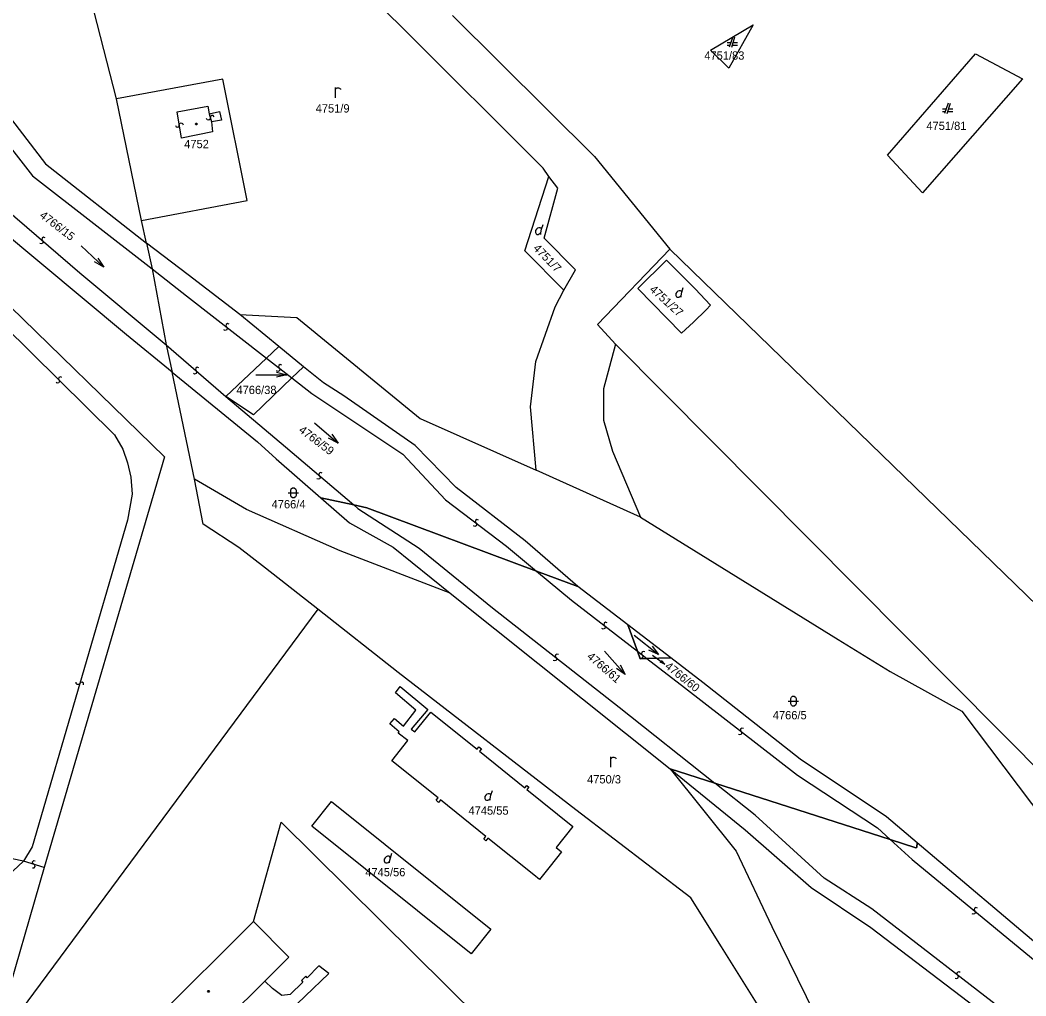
# Model space of a CAD drawing. Extents: x -266179 to -264727, y -1243225 to -1241702.
# Drawn here: x -265424.6 to -265230.4, y -1242086.5 to -1241898.2 of the extents above; entities that cross this region are included whole.
import ezdxf

# ---------------------------------------------------------------- set-up
doc = ezdxf.new("R2010")
doc.units = 0
doc.layers.add('Vrstva 1', color=7, linetype='Continuous')
doc.layers.add('Vrstva 2', color=7, linetype='Continuous')

msp = doc.modelspace()

# ---------------------------------------------------------------- linework, layer by layer
at = {"layer": 'Vrstva 1'}
for p, q in [((-265409.1, -1241901.41), (-265419.8, -1241859.01)), ((-265350.81, -1241899.67), (-265380.43, -1241870.51)), ((-265341.11, -1241897.34), (-265313.71, -1241924.53)), ((-265323.64, -1241926.77), (-265350.81, -1241899.67)), ((-265291.31, -1241904.02), (-265283.1, -1241899.12)), ((-265283.1, -1241899.12), (-265287.8, -1241907.53)), ((-265405.98, -1241913.4), (-265409.1, -1241901.41)), ((-265287.02, -1241901.44), (-265287.72, -1241903.44)), ((-265287.22, -1241903.44), (-265286.62, -1241901.44)), ((-265287.44, -1241902.64), (-265288.12, -1241902.64)), ((-265288.12, -1241903.04), (-265287.58, -1241903.04)), ((-265287.1, -1241903.04), (-265286.12, -1241903.04)), ((-265286.12, -1241902.64), (-265286.98, -1241902.64)), ((-265287.8, -1241907.53), (-265291.31, -1241904.02)), ((-265257.12, -1241924.32), (-265240.18, -1241904.71)), ((-265240.18, -1241904.71), (-265231.07, -1241909.59)), ((-265385.49, -1241909.62), (-265405.98, -1241913.4)), ((-265380.74, -1241933.05), (-265385.49, -1241909.62)), ((-265231.07, -1241909.59), (-265250.38, -1241931.54)), ((-265401.15, -1241936.9), (-265405.98, -1241913.4)), ((-265427.71, -1241915.45), (-265419.67, -1241925.96)), ((-265245.83, -1241915.44), (-265246.51, -1241915.44)), ((-265245.41, -1241914.24), (-265246.11, -1241916.24)), ((-265245.61, -1241916.24), (-265245.01, -1241914.24)), ((-265244.51, -1241915.44), (-265245.37, -1241915.44)), ((-265246.51, -1241915.84), (-265245.97, -1241915.84)), ((-265245.49, -1241915.84), (-265244.51, -1241915.84)), ((-265313.71, -1241924.53), (-265299.18, -1241942.46)), ((-265250.38, -1241931.54), (-265257.12, -1241924.32)), ((-265453.67, -1241927.03), (-265396.73, -1241982.53)), ((-265419.67, -1241925.96), (-265400.17, -1241941.28)), ((-265322.52, -1241928.38), (-265323.64, -1241926.77)), ((-265327.13, -1241942.78), (-265322.52, -1241928.38)), ((-265320.78, -1241930.65), (-265322.52, -1241928.38)), ((-265323.44, -1241940.32), (-265320.78, -1241930.65)), ((-265401.15, -1241936.9), (-265380.74, -1241933.05)), ((-265400.17, -1241941.28), (-265401.15, -1241936.9)), ((-265404.08, -1241958.98), (-265429.11, -1241938.09)), ((-265323.92, -1241938.58), (-265323.65, -1241937.68)), ((-265317.35, -1241946.43), (-265323.44, -1241940.32)), ((-265412.796, -1241941.764), (-265408.464, -1241945.916)), ((-265392.18, -1241947.36), (-265400.17, -1241941.28)), ((-265400.17, -1241941.28), (-265399.12, -1241946.23)), ((-265299.18, -1241942.46), (-265313.16, -1241956.94)), ((-265299.18, -1241942.46), (-265107.1, -1242128.74)), ((-265319.6, -1241950.32), (-265327.13, -1241942.78)), ((-265305.36, -1241950.05), (-265299.79, -1241944.58)), ((-265299.79, -1241944.58), (-265294.28, -1241950.11)), ((-265399.12, -1241946.23), (-265396.38, -1241960.9)), ((-265319.6, -1241950.32), (-265317.35, -1241946.43)), ((-265382.2, -1241955.06), (-265392.18, -1241947.36)), ((-265321.32, -1241953.55), (-265319.6, -1241950.32)), ((-265296.91, -1241958.67), (-265305.36, -1241950.05)), ((-265296.83, -1241950.72), (-265296.56, -1241949.82)), ((-265294.28, -1241950.11), (-265291.3, -1241953.23)), ((-265325.01, -1241964.12), (-265321.32, -1241953.55)), ((-265292.17, -1241954.15), (-265294.61, -1241956.49)), ((-265291.3, -1241953.23), (-265292.17, -1241954.15)), ((-265374.65, -1241961.21), (-265382.2, -1241955.06)), ((-265382.2, -1241955.06), (-265371.17, -1241955.6)), ((-265371.17, -1241955.6), (-265347.38, -1241975.13)), ((-265313.16, -1241956.94), (-265309.66, -1241960.74)), ((-265294.61, -1241956.49), (-265296.91, -1241958.67)), ((-265395.25, -1241966.18), (-265404.08, -1241958.98)), ((-265396.38, -1241960.9), (-265395.25, -1241966.18)), ((-265377.03, -1241963.45), (-265374.65, -1241961.21)), ((-265369.87, -1241965.11), (-265374.65, -1241961.21)), ((-265309.66, -1241960.74), (-265311.94, -1241969.4)), ((-265125.85, -1242145.82), (-265309.66, -1241960.74)), ((-265384.86, -1241970.84), (-265377.03, -1241963.45)), ((-265369.87, -1241965.11), (-265372.12, -1241967.27)), ((-265366.05, -1241968.22), (-265369.87, -1241965.11)), ((-265326.07, -1241972.85), (-265325.01, -1241964.12)), ((-265390.93, -1241986.84), (-265395.25, -1241966.18)), ((-265395.25, -1241966.18), (-265378.76, -1241979.64)), ((-265372.12, -1241967.27), (-265379.57, -1241974.41)), ((-265379.11, -1241966.65), (-265373.11, -1241966.65)), ((-265362.08, -1241970.73), (-265366.05, -1241968.22)), ((-265311.94, -1241969.4), (-265311.94, -1241975.4)), ((-265379.57, -1241974.41), (-265384.86, -1241970.84)), ((-265348.33, -1241980.33), (-265362.08, -1241970.73)), ((-265324.99, -1241985.06), (-265326.07, -1241972.85)), ((-265347.38, -1241975.13), (-265324.99, -1241985.06)), ((-265311.94, -1241975.4), (-265310.26, -1241981.4)), ((-265367.743, -1241975.922), (-265363.197, -1241979.838)), ((-265378.76, -1241979.64), (-265375.17, -1241982.89)), ((-265340.42, -1241988.44), (-265348.33, -1241980.33)), ((-265310.26, -1241981.4), (-265304.8, -1241994.15)), ((-265396.73, -1241982.53), (-265419.94, -1242061.77)), ((-265375.17, -1241982.89), (-265366.55, -1241990.42)), ((-265304.8, -1241994.15), (-265324.99, -1241985.06)), ((-265380.87, -1241992.68), (-265390.93, -1241986.84)), ((-265389.24, -1241995.49), (-265390.93, -1241986.84)), ((-265327.09, -1241998.73), (-265340.42, -1241988.44)), ((-265366.55, -1241990.42), (-265361.03, -1241995.25)), ((-265360.2, -1241991.78), (-265366.55, -1241990.42)), ((-265366.55, -1241990.42), (-265360.2, -1241991.78)), ((-265362.83, -1242000.62), (-265380.87, -1241992.68)), ((-265357.68, -1241992.32), (-265360.2, -1241991.78)), ((-265360.2, -1241991.78), (-265357.68, -1241992.32)), ((-265324.9, -1242004.54), (-265357.68, -1241992.32)), ((-265357.68, -1241992.32), (-265324.9, -1242004.54)), ((-265304.8, -1241994.15), (-265266.64, -1242017.73)), ((-265382.38, -1241999.97), (-265389.24, -1241995.49)), ((-265361.03, -1241995.25), (-265352.57, -1241999.96)), ((-265316.9, -1242007.52), (-265327.09, -1241998.73)), ((-265377.22, -1242004), (-265382.38, -1241999.97)), ((-265341.55, -1242008.84), (-265362.83, -1242000.62)), ((-265352.57, -1241999.96), (-265341.55, -1242008.84)), ((-265367.1, -1242011.91), (-265377.22, -1242004)), ((-265316.9, -1242007.52), (-265324.9, -1242004.54)), ((-265324.9, -1242004.54), (-265316.9, -1242007.52)), ((-265307.27, -1242014.93), (-265316.9, -1242007.52)), ((-265341.55, -1242008.84), (-265299.12, -1242042.71)), ((-265367.1, -1242011.91), (-265434.24, -1242102.45)), ((-265351.59, -1242024.1), (-265367.1, -1242011.91)), ((-265298.99, -1242021.3), (-265307.27, -1242014.93)), ((-265305.4, -1242020.02), (-265307.27, -1242014.93)), ((-265307.27, -1242014.93), (-265305.4, -1242020.02)), ((-265306.049, -1242016.946), (-265301.331, -1242020.654)), ((-265266.64, -1242017.73), (-265256.62, -1242023.96)), ((-265311.78, -1242020.024), (-265307.78, -1242024.496)), ((-265304.87, -1242021.46), (-265305.4, -1242020.02)), ((-265305.4, -1242020.02), (-265304.87, -1242021.46)), ((-265303.59, -1242021.43), (-265304.87, -1242021.46)), ((-265304.87, -1242021.46), (-265303.59, -1242021.43)), ((-265298.99, -1242021.3), (-265303.59, -1242021.43)), ((-265303.59, -1242021.43), (-265298.99, -1242021.3)), ((-265300.805, -1242021.781), (-265300.121, -1242022.538)), ((-265292.79, -1242026.07), (-265298.99, -1242021.3)), ((-265317.31, -1242050.61), (-265351.59, -1242024.1)), ((-265256.62, -1242023.96), (-265242.79, -1242031.59)), ((-265273.99, -1242040.84), (-265292.79, -1242026.07)), ((-265352.15, -1242028.05), (-265351.23, -1242026.82)), ((-265348.17, -1242031.4), (-265352.15, -1242028.05)), ((-265351.23, -1242026.82), (-265345.89, -1242031.24)), ((-265350.61, -1242034.5), (-265348.17, -1242031.4)), ((-265345.89, -1242031.24), (-265349.11, -1242035.03)), ((-265348.39, -1242035.56), (-265345.32, -1242031.75)), ((-265345.32, -1242031.75), (-265336.39, -1242038.94)), ((-265242.79, -1242031.59), (-265226.55, -1242053.07)), ((-265353.19, -1242034), (-265352.32, -1242032.98)), ((-265352.32, -1242032.98), (-265350.61, -1242034.5)), ((-265351.45, -1242035.57), (-265353.19, -1242034)), ((-265351.63, -1242035.85), (-265351.45, -1242035.57)), ((-265349.75, -1242037.24), (-265351.63, -1242035.85)), ((-265349.11, -1242035.03), (-265348.39, -1242035.56)), ((-265352.85, -1242041.14), (-265349.75, -1242037.24)), ((-265336.39, -1242038.94), (-265336.01, -1242038.47)), ((-265336.01, -1242038.47), (-265335.53, -1242038.86)), ((-265335.53, -1242038.86), (-265335.91, -1242039.33)), ((-265335.91, -1242039.33), (-265327.17, -1242046.37)), ((-265343.91, -1242048.32), (-265352.85, -1242041.14)), ((-265257.33, -1242052), (-265273.99, -1242040.84)), ((-265299.12, -1242042.71), (-265286.37, -1242058.58)), ((-265299.12, -1242042.71), (-265284.63, -1242054.46)), ((-265290.46, -1242045.49), (-265299.12, -1242042.71)), ((-265299.12, -1242042.71), (-265290.46, -1242045.49)), ((-265256.63, -1242056.36), (-265290.46, -1242045.49)), ((-265290.46, -1242045.49), (-265256.63, -1242056.36)), ((-265333.69, -1242047.79), (-265333.42, -1242046.89)), ((-265327.17, -1242046.37), (-265326.79, -1242045.9)), ((-265326.79, -1242045.9), (-265326.37, -1242046.24)), ((-265326.37, -1242046.24), (-265326.75, -1242046.7)), ((-265326.75, -1242046.7), (-265317.88, -1242053.85)), ((-265368.29, -1242053.78), (-265364.47, -1242049.02)), ((-265364.47, -1242049.02), (-265333.7, -1242073.65)), ((-265344.28, -1242048.79), (-265343.91, -1242048.32)), ((-265343.81, -1242049.19), (-265344.28, -1242048.79)), ((-265343.43, -1242048.71), (-265343.81, -1242049.19)), ((-265334.69, -1242055.74), (-265343.43, -1242048.71)), ((-265295.11, -1242067.63), (-265317.31, -1242050.61)), ((-265379.52, -1242072.17), (-265374.2, -1242053.02)), ((-265374.2, -1242053.02), (-265286.2, -1242140.05)), ((-265251.43, -1242056.99), (-265257.33, -1242052)), ((-265337.49, -1242078.4), (-265368.29, -1242053.78)), ((-265317.88, -1242053.85), (-265321.14, -1242057.9)), ((-265284.63, -1242054.46), (-265271.86, -1242065.62)), ((-265335.09, -1242056.22), (-265334.69, -1242055.74)), ((-265334.68, -1242056.58), (-265335.09, -1242056.22)), ((-265334.27, -1242056.08), (-265334.68, -1242056.58)), ((-265325.41, -1242063.2), (-265334.27, -1242056.08)), ((-265251.67, -1242057.95), (-265256.63, -1242056.36)), ((-265256.63, -1242056.36), (-265251.67, -1242057.95)), ((-265251.43, -1242056.99), (-265251.46, -1242057.82)), ((-265251.46, -1242057.82), (-265251.43, -1242056.99)), ((-265224.35, -1242079.9), (-265251.43, -1242056.99)), ((-265353.12, -1242059.86), (-265352.85, -1242058.96)), ((-265320.09, -1242058.75), (-265322.28, -1242061.48)), ((-265321.14, -1242057.9), (-265320.09, -1242058.75)), ((-265286.37, -1242058.58), (-265279.5, -1242073.11)), ((-265251.46, -1242057.82), (-265251.67, -1242057.95)), ((-265251.67, -1242057.95), (-265251.46, -1242057.82)), ((-265419.94, -1242061.77), (-265429.51, -1242094.71)), ((-265322.28, -1242061.48), (-265324.32, -1242064.08)), ((-265324.32, -1242064.08), (-265325.41, -1242063.2)), ((-265271.86, -1242065.62), (-265260.34, -1242073.33)), ((-265289.22, -1242077.06), (-265295.11, -1242067.63)), ((-265403.16, -1242095.63), (-265379.52, -1242072.17)), ((-265372.75, -1242079.05), (-265379.52, -1242072.17)), ((-265333.7, -1242073.65), (-265337.49, -1242078.4)), ((-265279.5, -1242073.11), (-265271.16, -1242090.08)), ((-265260.34, -1242073.33), (-265228.42, -1242097.62)), ((-265272.23, -1242104.07), (-265289.22, -1242077.06)), ((-265377.37, -1242083.7), (-265372.75, -1242079.05)), ((-265384.47, -1242100.74), (-265365.02, -1242082.22)), ((-265366.95, -1242080.73), (-265369.15, -1242083.05)), ((-265365.02, -1242082.22), (-265366.95, -1242080.73)), ((-265377.37, -1242083.7), (-265396.35, -1242102.47)), ((-265375.86, -1242085.08), (-265377.37, -1242083.7)), ((-265370.01, -1242083.9), (-265372.43, -1242086.29)), ((-265369.46, -1242082.73), (-265370.3, -1242083.57)), ((-265370.3, -1242083.57), (-265370.01, -1242083.9)), ((-265369.15, -1242083.05), (-265369.46, -1242082.73)), ((-265374.06, -1242086.44), (-265375.86, -1242085.08)), ((-265372.43, -1242086.29), (-265374.06, -1242086.44))]:
    msp.add_line(p, q, dxfattribs=at)
for points in [[(-265363.73, -1241913.2), (-265363.73, -1241911.93), (-265363.73, -1241911.2)], [(-265363.73, -1241911.6), (-265363.63, -1241911.47), (-265363.5, -1241911.36), (-265363.36, -1241911.31), (-265363.13, -1241911.3), (-265362.96, -1241911.33), (-265362.86, -1241911.4), (-265362.77, -1241911.5), (-265362.73, -1241911.6)], [(-265324.1, -1241939.57), (-265324.1, -1241939.3), (-265323.92, -1241938.58), (-265324.01, -1241938.4), (-265324.19, -1241938.31), (-265324.46, -1241938.31), (-265324.73, -1241938.4), (-265324.91, -1241938.58), (-265325.09, -1241938.85), (-265325.09, -1241939.21), (-265325, -1241939.48), (-265324.82, -1241939.57), (-265324.55, -1241939.57), (-265324.37, -1241939.48), (-265324.1, -1241939.3)], [(-265409.562, -1241944.171), (-265408.464, -1241945.916), (-265410.254, -1241944.893)], [(-265297.01, -1241951.71), (-265297.01, -1241951.44), (-265296.83, -1241950.72), (-265296.92, -1241950.54), (-265297.1, -1241950.45), (-265297.37, -1241950.45), (-265297.64, -1241950.54), (-265297.82, -1241950.72), (-265298, -1241950.99), (-265298, -1241951.35), (-265297.91, -1241951.62), (-265297.73, -1241951.71), (-265297.46, -1241951.71), (-265297.28, -1241951.62), (-265297.01, -1241951.44)], [(-265375.11, -1241966.15), (-265373.11, -1241966.65), (-265375.11, -1241967.15)], [(-265364.386, -1241978.154), (-265363.197, -1241979.838), (-265365.039, -1241978.912)], [(-265372.84, -1241989.45), (-265371.57, -1241989.45), (-265370.84, -1241989.45)], [(-265302.595, -1242019.025), (-265301.331, -1242020.654), (-265303.213, -1242019.811)], [(-265302.53, -1242020.75), (-265300.121, -1242022.538), (-265301.043, -1242022.102)], [(-265308.741, -1242022.672), (-265307.78, -1242024.496), (-265309.486, -1242023.339)], [(-265276.31, -1242029.66), (-265275.04, -1242029.66), (-265274.31, -1242029.66)], [(-265310.55, -1242042.38), (-265310.55, -1242041.11), (-265310.55, -1242040.38)], [(-265310.55, -1242040.78), (-265310.45, -1242040.65), (-265310.32, -1242040.54), (-265310.18, -1242040.49), (-265309.95, -1242040.48), (-265309.78, -1242040.51), (-265309.68, -1242040.58), (-265309.59, -1242040.68), (-265309.55, -1242040.78)], [(-265333.87, -1242048.78), (-265333.87, -1242048.51), (-265333.69, -1242047.79), (-265333.78, -1242047.61), (-265333.96, -1242047.52), (-265334.23, -1242047.52), (-265334.5, -1242047.61), (-265334.68, -1242047.79), (-265334.86, -1242048.06), (-265334.86, -1242048.42), (-265334.77, -1242048.69), (-265334.59, -1242048.78), (-265334.32, -1242048.78), (-265334.14, -1242048.69), (-265333.87, -1242048.51)], [(-265353.3, -1242060.85), (-265353.3, -1242060.58), (-265353.12, -1242059.86), (-265353.21, -1242059.68), (-265353.39, -1242059.59), (-265353.66, -1242059.59), (-265353.93, -1242059.68), (-265354.11, -1242059.86), (-265354.29, -1242060.13), (-265354.29, -1242060.49), (-265354.2, -1242060.76), (-265354.02, -1242060.85), (-265353.75, -1242060.85), (-265353.57, -1242060.76), (-265353.3, -1242060.58)]]:
    msp.add_lwpolyline(points, dxfattribs=at)
for points in [[(-265390.48, -1241918.14), (-265390.39, -1241918.29), (-265390.48, -1241918.44), (-265390.66, -1241918.44), (-265390.75, -1241918.29), (-265390.66, -1241918.14)], [(-265372.34, -1241988.95), (-265372.24, -1241988.66), (-265371.99, -1241988.48), (-265371.68, -1241988.48), (-265371.43, -1241988.66), (-265371.33, -1241988.95), (-265371.33, -1241989.95), (-265371.43, -1241990.24), (-265371.68, -1241990.42), (-265371.99, -1241990.42), (-265372.24, -1241990.24), (-265372.34, -1241989.95)], [(-265275.81, -1242029.16), (-265275.71, -1242028.87), (-265275.46, -1242028.69), (-265275.15, -1242028.69), (-265274.9, -1242028.87), (-265274.8, -1242029.16), (-265274.8, -1242030.16), (-265274.9, -1242030.45), (-265275.15, -1242030.63), (-265275.46, -1242030.63), (-265275.71, -1242030.45), (-265275.81, -1242030.16)], [(-265388.14, -1242085.5), (-265388.05, -1242085.65), (-265388.14, -1242085.8), (-265388.32, -1242085.8), (-265388.41, -1242085.65), (-265388.32, -1242085.5)]]:
    msp.add_lwpolyline(points, close=True, dxfattribs=at)
at = {"layer": 'Vrstva 2'}
for p, q in [((-265432.81, -1241914.75), (-265422.2, -1241928.26)), ((-265394.28, -1241915.94), (-265388.34, -1241914.84)), ((-265388.34, -1241914.84), (-265388.12, -1241916.29)), ((-265393.46, -1241921.03), (-265394.28, -1241915.94)), ((-265388.12, -1241916.29), (-265386.11, -1241915.87)), ((-265388.12, -1241916.29), (-265387.67, -1241917.87)), ((-265386.11, -1241915.87), (-265385.74, -1241917.52)), ((-265385.74, -1241917.52), (-265387.67, -1241917.87)), ((-265387.67, -1241917.87), (-265387.45, -1241919.79)), ((-265387.45, -1241919.79), (-265393.46, -1241921.03)), ((-265422.2, -1241928.26), (-265399.12, -1241946.23)), ((-265427.48, -1241934.56), (-265413.06, -1241946.99)), ((-265399.12, -1241946.23), (-265392.46, -1241951.42)), ((-265413.06, -1241946.99), (-265396.38, -1241960.9)), ((-265392.46, -1241951.42), (-265377.03, -1241963.45)), ((-265427.8, -1241957.08), (-265406.38, -1241978.28)), ((-265396.38, -1241960.9), (-265384.86, -1241970.84)), ((-265377.03, -1241963.45), (-265372.12, -1241967.27)), ((-265372.12, -1241967.27), (-265368.29, -1241970.26)), ((-265384.86, -1241970.84), (-265373.36, -1241980.58)), ((-265368.29, -1241970.26), (-265350.69, -1241982.01)), ((-265406.38, -1241978.28), (-265404.74, -1241981.03)), ((-265404.74, -1241981.03), (-265403.85, -1241983.68)), ((-265373.36, -1241980.58), (-265360.2, -1241991.78)), ((-265350.69, -1241982.01), (-265342.48, -1241990.81)), ((-265403.85, -1241983.68), (-265403.24, -1241986.42)), ((-265403.24, -1241986.42), (-265402.99, -1241989.71)), ((-265402.99, -1241989.71), (-265403.87, -1241994.7)), ((-265342.48, -1241990.81), (-265330.7, -1241999.72)), ((-265360.2, -1241991.78), (-265359.4, -1241992.46)), ((-265359.4, -1241992.46), (-265347.58, -1242000.14)), ((-265403.87, -1241994.7), (-265422.27, -1242057.76)), ((-265347.58, -1242000.14), (-265333.39, -1242011.63)), ((-265330.7, -1241999.72), (-265324.9, -1242004.54)), ((-265324.9, -1242004.54), (-265318.14, -1242010.15)), ((-265318.14, -1242010.15), (-265305.4, -1242020.02)), ((-265333.39, -1242011.63), (-265308.92, -1242030.83)), ((-265305.4, -1242020.02), (-265303.59, -1242021.43)), ((-265303.59, -1242021.43), (-265296.33, -1242027.05)), ((-265296.33, -1242027.05), (-265274.52, -1242043.96)), ((-265308.92, -1242030.83), (-265290.46, -1242045.49)), ((-265282.68, -1242051.67), (-265290.46, -1242045.49)), ((-265274.52, -1242043.96), (-265259.1, -1242054.13)), ((-265269.38, -1242063.81), (-265282.68, -1242051.67)), ((-265259.1, -1242054.13), (-265256.63, -1242056.36)), ((-265256.63, -1242056.36), (-265252.36, -1242060.2)), ((-265422.27, -1242057.76), (-265423.95, -1242060.52)), ((-265423.95, -1242060.52), (-265430.56, -1242066.66)), ((-265423.95, -1242060.52), (-265426.12, -1242060.07)), ((-265419.94, -1242061.77), (-265423.95, -1242060.52)), ((-265252.36, -1242060.2), (-265228.25, -1242080.06)), ((-265260.16, -1242069.72), (-265269.38, -1242063.81)), ((-265227.01, -1242095.32), (-265260.16, -1242069.72))]:
    msp.add_line(p, q, dxfattribs=at)
for points in [[(-265387.16, -1241916.923), (-265387.351, -1241916.655), (-265387.669, -1241916.631), (-265387.871, -1241916.834), (-265387.927, -1241917.37), (-265388.188, -1241917.548), (-265388.491, -1241917.468), (-265388.63, -1241917.237)], [(-265394.618, -1241918.555), (-265394.46, -1241918.844), (-265394.147, -1241918.904), (-265393.922, -1241918.726), (-265393.804, -1241918.201), (-265393.524, -1241918.054), (-265393.232, -1241918.169), (-265393.122, -1241918.415)], [(-265419.743, -1241940.239), (-265420.049, -1241940.12), (-265420.328, -1241940.276), (-265420.385, -1241940.557), (-265420.137, -1241941.035), (-265420.257, -1241941.327), (-265420.555, -1241941.427), (-265420.797, -1241941.311)], [(-265384.244, -1241956.874), (-265384.557, -1241956.77), (-265384.828, -1241956.939), (-265384.871, -1241957.223), (-265384.6, -1241957.688), (-265384.705, -1241957.986), (-265384.997, -1241958.1), (-265385.246, -1241957.996)], [(-265390.092, -1241965.335), (-265390.399, -1241965.216), (-265390.678, -1241965.371), (-265390.735, -1241965.652), (-265390.488, -1241966.13), (-265390.608, -1241966.422), (-265390.905, -1241966.522), (-265391.148, -1241966.405)], [(-265374.075, -1241964.799), (-265374.387, -1241964.695), (-265374.658, -1241964.864), (-265374.701, -1241965.148), (-265374.429, -1241965.613), (-265374.535, -1241965.911), (-265374.827, -1241966.026), (-265375.075, -1241965.921)], [(-265416.527, -1241967.182), (-265416.825, -1241967.042), (-265417.114, -1241967.178), (-265417.19, -1241967.454), (-265416.975, -1241967.948), (-265417.115, -1241968.232), (-265417.419, -1241968.311), (-265417.653, -1241968.178)], [(-265366.256, -1241985.641), (-265366.563, -1241985.524), (-265366.841, -1241985.681), (-265366.897, -1241985.962), (-265366.646, -1241986.439), (-265366.764, -1241986.732), (-265367.061, -1241986.834), (-265367.304, -1241986.719)], [(-265336.098, -1241994.697), (-265336.412, -1241994.598), (-265336.68, -1241994.771), (-265336.719, -1241995.055), (-265336.441, -1241995.516), (-265336.542, -1241995.815), (-265336.832, -1241995.934), (-265337.082, -1241995.833)], [(-265311.271, -1242014.523), (-265311.584, -1242014.42), (-265311.854, -1242014.59), (-265311.897, -1242014.873), (-265311.624, -1242015.337), (-265311.729, -1242015.636), (-265312.02, -1242015.751), (-265312.269, -1242015.647)], [(-265303.994, -1242020.164), (-265304.307, -1242020.06), (-265304.578, -1242020.229), (-265304.621, -1242020.513), (-265304.35, -1242020.978), (-265304.455, -1242021.276), (-265304.747, -1242021.39), (-265304.996, -1242021.286)], [(-265320.653, -1242020.671), (-265320.965, -1242020.566), (-265321.236, -1242020.734), (-265321.28, -1242021.017), (-265321.01, -1242021.483), (-265321.117, -1242021.781), (-265321.409, -1242021.895), (-265321.657, -1242021.789)], [(-265412.364, -1242026.488), (-265412.383, -1242026.16), (-265412.64, -1242025.97), (-265412.919, -1242026.034), (-265413.251, -1242026.458), (-265413.567, -1242026.47), (-265413.782, -1242026.241), (-265413.776, -1242025.972)], [(-265284.926, -1242034.943), (-265285.239, -1242034.84), (-265285.509, -1242035.01), (-265285.552, -1242035.293), (-265285.279, -1242035.757), (-265285.384, -1242036.056), (-265285.675, -1242036.171), (-265285.924, -1242036.067)], [(-265422.216, -1242061.846), (-265421.888, -1242061.833), (-265421.693, -1242061.58), (-265421.752, -1242061.299), (-265422.17, -1242060.96), (-265422.176, -1242060.643), (-265421.943, -1242060.433), (-265421.674, -1242060.444)], [(-265239.789, -1242069.583), (-265240.099, -1242069.471), (-265240.374, -1242069.632), (-265240.425, -1242069.914), (-265240.167, -1242070.387), (-265240.28, -1242070.682), (-265240.575, -1242070.788), (-265240.821, -1242070.677)], [(-265244.083, -1242083.083), (-265243.77, -1242083.185), (-265243.5, -1242083.015), (-265243.458, -1242082.732), (-265243.731, -1242082.268), (-265243.627, -1242081.969), (-265243.336, -1242081.853), (-265243.087, -1242081.957)]]:
    msp.add_lwpolyline(points, dxfattribs=at)

# ---------------------------------------------------------------- texts
at = {"layer": 'Vrstva 1'}
for s, p in [('4751/83', (-265292.508, -1241905.86)), ('4751/9', (-265367.536, -1241916.06)), ('4751/81', (-265249.639, -1241919.43)), ('4752', (-265392.918, -1241922.94)), ('4766/38', (-265382.829, -1241970.39)), ('4766/4', (-265376.041, -1241992.45)), ('4766/5', (-265279.291, -1242033.16)), ('4750/3', (-265315.142, -1242045.53)), ('4745/55', (-265338.031, -1242051.56)), ('4745/56', (-265357.955, -1242063.45))]:
    msp.add_text(s, height=1.6, dxfattribs=at).set_placement(p)
for s, rotation, p in [('4766/15', 322.46065, (-265420.956, -1241936.178)), ('4751/7', 314.21006, (-265325.669, -1241942.363)), ('4751/27', 317.76239, (-265303.207, -1241950.392)), ('4766/59', 322.86172, (-265370.933, -1241977.612)), ('4766/61', 319.25208, (-265315.301, -1242021.256)), ('4766/60', 321.31473, (-265300.248, -1242023.163))]:
    msp.add_text(s, height=1.6, rotation=rotation, dxfattribs=at).set_placement(p)

doc.saveas('drawing.dxf')
